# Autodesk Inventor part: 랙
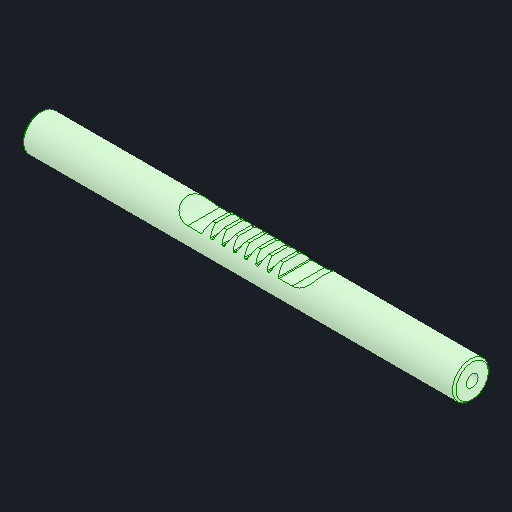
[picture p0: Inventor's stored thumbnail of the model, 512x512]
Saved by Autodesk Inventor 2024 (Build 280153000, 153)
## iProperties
Created: 2024-05
Part Number: 랙
Material: 강철, 탄소
Document SubType Name: Modeling
Designer: kh_501
Density: 7.85 g/cm^3
Appearance: 기본값
Sending System: Autodesk Inventor 2025
Preprocessor: ST-DEVELOPER v20
Author: jhkim
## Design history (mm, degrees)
feature "솔리드1"
node "솔리드2"
